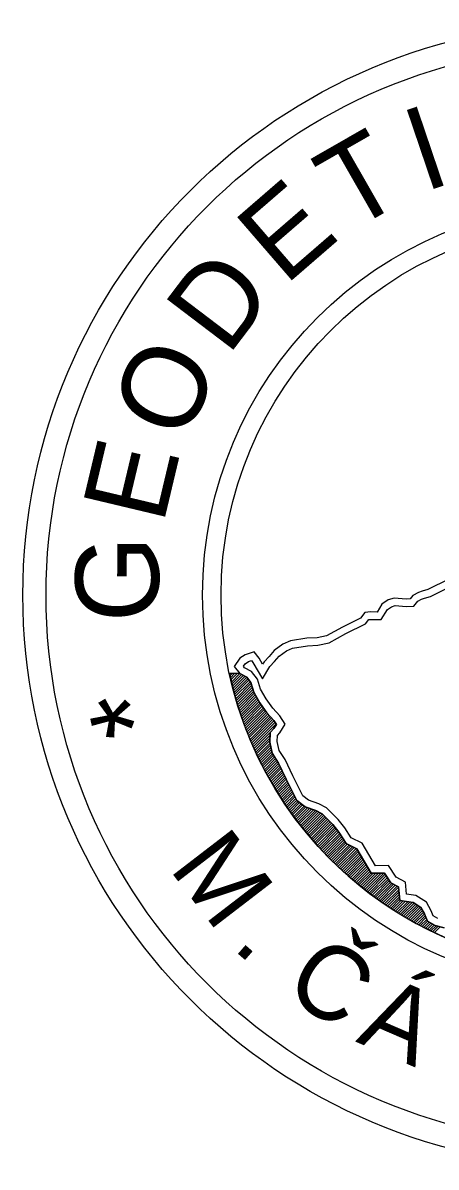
# Model space of a CAD drawing. Extents: x -823399 to -812899, y -1074543 to -1067118.
# Drawn here: x -814729.2 to -814581.1, y -1071654.2 to -1071244.4 of the extents above; entities that cross this region are included whole.
import ezdxf

# ---------------------------------------------------------------- set-up
doc = ezdxf.new("R2010")
doc.units = 0
doc.layers.add('Vrstva 63', color=7, linetype='Continuous')

msp = doc.modelspace()

# ---------------------------------------------------------------- linework, layer by layer
at = {"layer": 'Vrstva 63'}
for p, q in [((-814651.48, -1071477.46), (-814655.2, -1071477.43)), ((-814651.48, -1071477.46), (-814655.2, -1071477.43)), ((-814655.2, -1071477.44), (-814655.19, -1071477.43)), ((-814655.03, -1071478.22), (-814654.26, -1071477.44)), ((-814654.86, -1071478.98), (-814653.33, -1071477.45)), ((-814654.69, -1071479.75), (-814652.39, -1071477.45)), ((-814654.51, -1071480.51), (-814651.47, -1071477.47)), ((-814654.32, -1071481.26), (-814650.85, -1071477.79)), ((-814654.14, -1071482.01), (-814650.24, -1071478.12)), ((-814653.94, -1071482.76), (-814649.62, -1071478.44)), ((-814653.75, -1071483.51), (-814649.01, -1071478.76)), ((-814653.55, -1071484.25), (-814648.6, -1071479.3)), ((-814653.35, -1071484.99), (-814648.2, -1071479.83)), ((-814653.14, -1071485.72), (-814647.79, -1071480.37)), ((-814652.94, -1071486.45), (-814647.47, -1071480.98)), ((-814652.72, -1071487.18), (-814647.25, -1071481.7)), ((-814652.51, -1071487.9), (-814647.03, -1071482.42)), ((-814652.29, -1071488.62), (-814646.81, -1071483.14)), ((-814652.07, -1071489.34), (-814646.59, -1071483.86)), ((-814651.84, -1071490.05), (-814646.29, -1071484.5)), ((-814651.61, -1071490.76), (-814645.94, -1071485.09)), ((-814651.38, -1071491.47), (-814645.59, -1071485.68)), ((-814651.14, -1071492.18), (-814645.24, -1071486.27)), ((-814650.9, -1071492.88), (-814644.89, -1071486.86)), ((-814650.66, -1071493.57), (-814644.54, -1071487.45)), ((-814650.42, -1071494.27), (-814644.18, -1071488.03)), ((-814650.17, -1071494.96), (-814643.79, -1071488.58)), ((-814649.92, -1071495.65), (-814643.41, -1071489.14)), ((-814649.66, -1071496.33), (-814643.02, -1071489.69)), ((-814649.4, -1071497.01), (-814642.63, -1071490.24)), ((-814649.14, -1071497.69), (-814642.25, -1071490.79)), ((-814648.88, -1071498.37), (-814641.86, -1071491.34)), ((-814648.61, -1071499.04), (-814641.43, -1071491.85)), ((-814648.34, -1071499.71), (-814640.98, -1071492.34)), ((-814648.07, -1071500.38), (-814640.53, -1071492.83)), ((-814647.79, -1071501.04), (-814640.08, -1071493.32)), ((-814647.52, -1071501.7), (-814639.63, -1071493.81)), ((-814647.23, -1071502.36), (-814639.19, -1071494.32)), ((-814646.95, -1071503.01), (-814638.82, -1071494.89)), ((-814646.66, -1071503.66), (-814638.45, -1071495.45)), ((-814646.37, -1071504.31), (-814639.88, -1071497.82)), ((-814646.08, -1071504.96), (-814640.59, -1071499.47)), ((-814645.78, -1071505.6), (-814640.64, -1071500.46)), ((-814645.48, -1071506.24), (-814640.69, -1071501.45)), ((-814645.18, -1071506.88), (-814640.64, -1071502.34)), ((-814644.88, -1071507.52), (-814640.48, -1071503.12)), ((-814644.57, -1071508.15), (-814640.32, -1071503.89)), ((-814644.26, -1071508.78), (-814640.15, -1071504.67)), ((-814643.95, -1071509.4), (-814639.99, -1071505.45)), ((-814643.63, -1071510.03), (-814639.77, -1071506.17)), ((-814643.31, -1071510.65), (-814639.4, -1071506.73)), ((-814642.99, -1071511.27), (-814639.03, -1071507.3)), ((-814642.67, -1071511.88), (-814638.65, -1071507.87)), ((-814642.34, -1071512.5), (-814638.28, -1071508.44)), ((-814642.01, -1071513.11), (-814637.91, -1071509.01)), ((-814641.68, -1071513.72), (-814637.54, -1071509.58)), ((-814641.35, -1071514.32), (-814637.24, -1071510.21)), ((-814641.01, -1071514.92), (-814636.94, -1071510.85)), ((-814640.67, -1071515.52), (-814636.64, -1071511.49)), ((-814640.33, -1071516.12), (-814636.34, -1071512.13)), ((-814639.99, -1071516.72), (-814636.03, -1071512.77)), ((-814639.64, -1071517.31), (-814635.73, -1071513.4)), ((-814639.29, -1071517.9), (-814635.43, -1071514.04)), ((-814638.94, -1071518.49), (-814635.13, -1071514.68)), ((-814638.58, -1071519.07), (-814634.83, -1071515.32)), ((-814638.22, -1071519.65), (-814634.51, -1071515.94)), ((-814637.86, -1071520.23), (-814634.2, -1071516.57)), ((-814637.5, -1071520.81), (-814633.89, -1071517.2)), ((-814637.14, -1071521.38), (-814633.58, -1071517.83)), ((-814636.77, -1071521.96), (-814633.27, -1071518.45)), ((-814636.4, -1071522.53), (-814632.95, -1071519.08)), ((-814636.03, -1071523.09), (-814632.64, -1071519.71)), ((-814635.65, -1071523.66), (-814632.33, -1071520.34)), ((-814635.28, -1071524.22), (-814632.02, -1071520.96)), ((-814634.9, -1071524.78), (-814631.71, -1071521.59)), ((-814634.51, -1071525.34), (-814631.39, -1071522.22)), ((-814634.13, -1071525.89), (-814631.08, -1071522.84)), ((-814633.74, -1071526.44), (-814630.58, -1071523.29)), ((-814633.35, -1071526.99), (-814630.05, -1071523.69)), ((-814632.96, -1071527.54), (-814629.52, -1071524.1)), ((-814632.57, -1071528.09), (-814628.99, -1071524.51)), ((-814632.17, -1071528.63), (-814628.46, -1071524.92)), ((-814631.77, -1071529.17), (-814627.88, -1071525.28)), ((-814631.37, -1071529.71), (-814627.18, -1071525.52)), ((-814630.96, -1071530.24), (-814626.48, -1071525.76)), ((-814630.56, -1071530.77), (-814625.78, -1071526)), ((-814630.15, -1071531.31), (-814625.08, -1071526.24)), ((-814629.74, -1071531.83), (-814624.38, -1071526.48)), ((-814629.32, -1071532.36), (-814623.74, -1071526.78)), ((-814628.91, -1071532.88), (-814623.12, -1071527.09)), ((-814628.49, -1071533.4), (-814622.5, -1071527.41)), ((-814628.07, -1071533.92), (-814621.91, -1071527.76)), ((-814627.65, -1071534.44), (-814621.44, -1071528.24)), ((-814627.22, -1071534.95), (-814620.98, -1071528.71)), ((-814626.79, -1071535.46), (-814620.51, -1071529.18)), ((-814626.36, -1071535.97), (-814620.04, -1071529.65)), ((-814625.93, -1071536.48), (-814619.58, -1071530.13)), ((-814625.49, -1071536.99), (-814619.11, -1071530.6)), ((-814625.06, -1071537.49), (-814618.64, -1071531.07)), ((-814624.62, -1071537.99), (-814618.18, -1071531.55)), ((-814624.18, -1071538.48), (-814617.75, -1071532.06)), ((-814623.73, -1071538.98), (-814617.33, -1071532.58)), ((-814623.28, -1071539.47), (-814616.9, -1071533.09)), ((-814622.84, -1071539.96), (-814616.47, -1071533.6)), ((-814622.38, -1071540.45), (-814616.05, -1071534.12)), ((-814621.93, -1071540.94), (-814615.67, -1071534.68)), ((-814621.47, -1071541.42), (-814615.31, -1071535.26)), ((-814621.02, -1071541.9), (-814614.95, -1071535.83)), ((-814620.56, -1071542.38), (-814614.59, -1071536.41)), ((-814620.09, -1071542.86), (-814614.22, -1071536.99)), ((-814619.63, -1071543.33), (-814613.86, -1071537.57)), ((-814619.16, -1071543.8), (-814613.5, -1071538.14)), ((-814618.69, -1071544.27), (-814612.96, -1071538.55)), ((-814618.22, -1071544.74), (-814612.33, -1071538.86)), ((-814617.74, -1071545.2), (-814611.7, -1071539.16)), ((-814617.27, -1071545.67), (-814611.07, -1071539.47)), ((-814616.79, -1071546.13), (-814610.44, -1071539.78)), ((-814616.3, -1071546.59), (-814609.81, -1071540.09)), ((-814615.82, -1071547.04), (-814609.35, -1071540.57)), ((-814615.33, -1071547.49), (-814609, -1071541.16)), ((-814614.85, -1071547.95), (-814608.65, -1071541.75)), ((-814614.36, -1071548.39), (-814608.3, -1071542.33)), ((-814613.86, -1071548.84), (-814607.95, -1071542.92)), ((-814613.37, -1071549.28), (-814607.59, -1071543.51)), ((-814612.87, -1071549.73), (-814607.24, -1071544.1)), ((-814612.37, -1071550.16), (-814606.89, -1071544.69)), ((-814611.87, -1071550.6), (-814606.54, -1071545.28)), ((-814611.36, -1071551.04), (-814606.19, -1071545.87)), ((-814610.85, -1071551.47), (-814605.84, -1071546.46)), ((-814610.34, -1071551.9), (-814605.49, -1071547.04)), ((-814609.83, -1071552.32), (-814605.14, -1071547.63)), ((-814609.32, -1071552.75), (-814604.79, -1071548.22)), ((-814608.8, -1071553.17), (-814604.44, -1071548.81)), ((-814608.28, -1071553.59), (-814603.63, -1071548.95)), ((-814607.76, -1071554.01), (-814602.69, -1071548.94)), ((-814607.24, -1071554.43), (-814601.74, -1071548.93)), ((-814606.71, -1071554.84), (-814600.8, -1071548.93)), ((-814606.18, -1071555.25), (-814599.85, -1071548.92)), ((-814605.65, -1071555.66), (-814599.34, -1071549.35)), ((-814605.12, -1071556.06), (-814598.97, -1071549.92)), ((-814604.58, -1071556.47), (-814598.59, -1071550.48)), ((-814604.04, -1071556.87), (-814598.22, -1071551.05)), ((-814603.5, -1071557.27), (-814597.85, -1071551.61)), ((-814602.96, -1071557.66), (-814597.47, -1071552.18)), ((-814602.41, -1071558.06), (-814596.95, -1071552.6)), ((-814601.86, -1071558.45), (-814596.34, -1071552.93)), ((-814601.31, -1071558.84), (-814595.74, -1071553.26)), ((-814600.76, -1071559.23), (-814595.13, -1071553.6)), ((-814600.21, -1071559.61), (-814594.61, -1071554.02)), ((-814599.65, -1071559.99), (-814594.53, -1071554.88)), ((-814599.09, -1071560.37), (-814594.46, -1071555.74)), ((-814598.53, -1071560.75), (-814594.38, -1071556.6)), ((-814597.96, -1071561.12), (-814594.3, -1071557.46)), ((-814597.39, -1071561.49), (-814594.22, -1071558.32)), ((-814596.82, -1071561.86), (-814593.74, -1071558.78)), ((-814596.25, -1071562.23), (-814592.93, -1071558.91)), ((-814595.68, -1071562.6), (-814592.12, -1071559.03)), ((-814595.1, -1071562.96), (-814591.3, -1071559.16)), ((-814594.52, -1071563.32), (-814590.49, -1071559.29)), ((-814593.94, -1071563.67), (-814589.67, -1071559.41)), ((-814593.35, -1071564.03), (-814589.01, -1071559.68)), ((-814592.76, -1071564.38), (-814588.43, -1071560.04)), ((-814592.17, -1071564.73), (-814587.84, -1071560.4)), ((-814591.58, -1071565.08), (-814587.26, -1071560.76)), ((-814590.98, -1071565.42), (-814586.68, -1071561.12)), ((-814590.39, -1071565.76), (-814586.3, -1071561.67)), ((-814589.79, -1071566.1), (-814585.97, -1071562.29)), ((-814589.18, -1071566.44), (-814585.65, -1071562.9)), ((-814588.58, -1071566.77), (-814585.32, -1071563.51)), ((-814587.97, -1071567.1), (-814585.05, -1071564.18)), ((-814587.36, -1071567.43), (-814584.77, -1071564.84)), ((-814586.74, -1071567.75), (-814584.5, -1071565.51)), ((-814586.13, -1071568.08), (-814584.18, -1071566.13)), ((-814585.51, -1071568.4), (-814583.59, -1071566.48)), ((-814584.89, -1071568.72), (-814582.99, -1071566.82)), ((-814584.26, -1071569.03), (-814582.4, -1071567.17)), ((-814583.63, -1071569.34), (-814581.81, -1071567.52)), ((-814583, -1071569.65), (-814581.13, -1071567.78)), ((-814582.37, -1071569.96), (-814580.37, -1071567.96)), ((-814581.74, -1071570.26), (-814579.61, -1071568.14))]:
    msp.add_line(p, q, dxfattribs=at)
for points in [[(-814576.6, -1071443.59), (-814584.08, -1071447.35), (-814586.12, -1071447.95), (-814587.4, -1071448.37), (-814589.41, -1071449.44), (-814590.43, -1071450.69), (-814591.82, -1071450.74), (-814596.11, -1071450.43), (-814598.31, -1071451.06), (-814600.53, -1071452.64), (-814602.27, -1071455.4), (-814604.53, -1071455.39), (-814606.61, -1071455.56), (-814608.19, -1071457.56), (-814614.71, -1071460.78), (-814620.37, -1071463.92), (-814623.8, -1071464.6), (-814627.48, -1071464.81), (-814633.29, -1071465.77), (-814636.1, -1071466.92), (-814639.17, -1071469.22), (-814640.99, -1071471.38), (-814642.79, -1071473.3), (-814643.31, -1071474.13), (-814644.55, -1071471.99), (-814646.28, -1071469.67), (-814649.54, -1071470.71), (-814651.45, -1071471.97), (-814653.51, -1071474.88), (-814651.48, -1071477.46), (-814649.01, -1071478.76), (-814647.56, -1071480.68), (-814646.5, -1071484.16), (-814644.25, -1071487.94), (-814641.74, -1071491.52), (-814639.25, -1071494.23), (-814638.33, -1071495.64), (-814639.24, -1071497.09), (-814640.54, -1071498.58), (-814640.72, -1071501.97), (-814639.88, -1071506), (-814637.55, -1071509.56), (-814634.87, -1071515.23), (-814631.04, -1071522.94), (-814628.08, -1071525.21), (-814624.22, -1071526.54), (-814622.01, -1071527.66), (-814618.19, -1071531.53), (-814615.96, -1071534.22), (-814613.37, -1071538.35), (-814609.56, -1071540.21), (-814604.36, -1071548.95), (-814599.62, -1071548.92), (-814597.34, -1071552.38), (-814594.63, -1071553.88), (-814594.18, -1071558.72), (-814589.37, -1071559.46), (-814586.56, -1071561.19), (-814585.31, -1071563.52), (-814584.26, -1071566.09), (-814581.49, -1071567.7), (-814578.21, -1071568.47)], [(-814580.5, -1071565.2), (-814582.15, -1071564.24), (-814582.91, -1071562.39), (-814584.55, -1071559.31), (-814588.44, -1071556.92), (-814591.73, -1071556.41), (-814592.11, -1071552.23), (-814595.48, -1071550.37), (-814598.2, -1071546.25), (-814602.85, -1071546.28), (-814607.68, -1071538.18), (-814611.52, -1071536.29), (-814613.81, -1071532.65), (-814616.22, -1071529.75), (-814620.42, -1071525.49), (-814623.18, -1071524.08), (-814626.81, -1071522.84), (-814628.93, -1071521.21), (-814632.48, -1071514.08), (-814635.22, -1071508.26), (-814637.38, -1071504.97), (-814638.05, -1071501.76), (-814637.94, -1071499.64), (-814637.1, -1071498.68), (-814635.19, -1071495.6), (-814637.14, -1071492.59), (-814639.66, -1071489.85), (-814642.01, -1071486.5), (-814644.05, -1071483.07), (-814645.16, -1071479.45), (-814647.25, -1071476.69), (-814649.74, -1071475.37), (-814650.19, -1071474.8), (-814649.56, -1071473.91), (-814648.38, -1071473.13), (-814647.28, -1071472.78), (-814646.77, -1071473.45), (-814643.39, -1071479.3), (-814640.68, -1071474.93), (-814639, -1071473.15), (-814637.34, -1071471.16), (-814634.78, -1071469.25), (-814632.56, -1071468.35), (-814627.19, -1071467.46), (-814623.46, -1071467.24), (-814619.44, -1071466.45), (-814613.47, -1071463.14), (-814606.47, -1071459.67), (-814605.24, -1071458.11), (-814604.43, -1071458.04), (-814600.81, -1071458.07), (-814598.56, -1071454.5), (-814597.15, -1071453.49), (-814595.83, -1071453.12), (-814591.88, -1071453.4), (-814589.12, -1071453.31), (-814587.68, -1071451.53), (-814586.36, -1071450.82), (-814585.34, -1071450.49), (-814583.1, -1071449.83), (-814575.69, -1071446.11)], [(-814578.21, -1071568.47), (-814581.49, -1071567.7), (-814584.26, -1071566.09), (-814585.31, -1071563.52), (-814586.56, -1071561.19), (-814589.37, -1071559.46), (-814594.18, -1071558.72), (-814594.63, -1071553.88), (-814597.34, -1071552.38), (-814599.62, -1071548.92), (-814604.36, -1071548.95), (-814609.56, -1071540.21), (-814613.37, -1071538.35), (-814615.96, -1071534.22), (-814618.19, -1071531.53), (-814622.01, -1071527.66), (-814624.22, -1071526.54), (-814628.08, -1071525.21), (-814631.04, -1071522.94), (-814634.87, -1071515.23), (-814637.55, -1071509.56), (-814639.88, -1071506), (-814640.72, -1071501.97), (-814640.54, -1071498.58), (-814639.24, -1071497.09), (-814638.33, -1071495.64), (-814639.25, -1071494.23), (-814641.74, -1071491.52), (-814644.25, -1071487.94), (-814646.5, -1071484.16), (-814647.56, -1071480.68), (-814649.01, -1071478.76), (-814651.48, -1071477.46)]]:
    msp.add_lwpolyline(points, dxfattribs=at)
for radius in [204.94, 196.63, 196.63, 140.55, 140.55, 133.91]:
    msp.add_circle((-814524.28, -1071449.31), radius, dxfattribs=at)
msp.add_arc((-814524.28, -1071449.31), 133.91, 192.1248, 329.9318, dxfattribs=at)

# ---------------------------------------------------------------- texts
for s, height, rotation, p in [('I', 29.89, 18.7306, (-814585.47, -1071305.05)), ('T', 29.89, 29.797, (-814612.02, -1071319.48)), ('E', 29.89, 40.8634, (-814635.31, -1071338.73)), ('D', 29.89, 52.7843, (-814655.75, -1071364.05)), ('O', 29.89, 65.5492, (-814671.34, -1071395.21)), ('E', 29.89, 76.6156, (-814678.99, -1071424.44)), ('G', 29.89, 89.3804, (-814680.66, -1071459.24)), ('*', 29.89, 103.0104, (-814673.92, -1071495.81)), ('M', 26.57, 307.5302, (-814677.14, -1071547.23)), ('Č', 26.57, 326.6696, (-814636.59, -1071591.93)), ('.', 26.57, 319.0138, (-814654.59, -1071575.7)), ('Á', 26.57, 336.6266, (-814610.23, -1071609.2))]:
    msp.add_text(s, height=height, rotation=rotation, dxfattribs=at).set_placement(p)

doc.saveas('drawing.dxf')
